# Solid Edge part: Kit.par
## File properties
Author: bmolnar
Last saved by: bmolnar
Revision: 78
Sűrűség: 0,000 kg/m^3
Pontosság: 0,990
Username: bmolnar
Dokumentum tartalom típus: 0
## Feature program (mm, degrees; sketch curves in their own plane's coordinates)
base feature "unnamed BaseFeature 1"
sketch for "unnamed Hole 1" plane through (36, 36, -84) normal (0, 0, -1) x-axis (0, -1, 0)
  hole centre (0, 0) bore radius 4.188
hole "unnamed Hole 1" through
sketch for "unnamed Hole 2" plane through (36, 36, -84) normal (0, 0, -1) x-axis (0, -1, 0)
  hole centre (0, 72) bore radius 4.188
hole "unnamed Hole 2" through
sketch for "unnamed Hole 3" plane through (36, 36, -84) normal (0, 0, -1) x-axis (0, -1, 0)
  hole centre (72, 72) bore radius 4.188
hole "unnamed Hole 3" through
sketch for "unnamed Hole 4" plane through (36, 36, -84) normal (0, 0, -1) x-axis (0, -1, 0)
  hole centre (72, 0) bore radius 4.188
hole "unnamed Hole 4" through
pattern "unnamed Pattern 1" of "unnamed Hole 1", "unnamed Hole 2", "unnamed Hole 3", "unnamed Hole 4"
sketch for "Furat_6" plane through (-47.6845, 0, -79.5) normal (-0.999962, 0, -0.008727) x-axis (0, -1, 0)
  hole centre (-0.0008, 0.4997) bore radius 4.283
hole "Furat_6" nominal diameter 9.728 finite  ThreadDepth = 10 mm
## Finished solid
Body 1: solid body, 307 faces, 739 edges, 449 vertices.
  Faces by surface: plane 139, cylinder 73, swept 60, cone 24, torus 10, spline 1
  Edges by curve: line 421, circle 152, spline 120, ellipse 32, curve on surface 14
Bounding box of the edges (mm; curved faces can reach further): 95.500 x 95.500 x 15.000, from (-47.75, -47.75, -87) to (47.75, 47.75, -72).
Cylindrical faces by radius (mm): R0.2 x48, R0.2017 x2, R0.2018 x2, R4.188 x4, R4.283 x1, R4.9 x4, R5.15 x4, R6.75 x4, R10.3 x1, R10.95 x1, R11.5 x1, R12.5 x1
Conical faces (half-angle, radius in mm at the cone's reference point): 0.5 deg R10 x4, 0.5 deg R13.5 x2, 7 deg R11.7695 x1, 14 deg R10.15 x1, 14 deg R10.557 x1, 17 deg R10.15 x1, 23 deg R10.9211 x1, 42.5 deg R10.137 x1, 45 deg R4.185 x4, 45 deg R4.985 x4, 45 deg R11.1 x1, 84 deg R10.512 x1, 85 deg R12.1625 x1, 87 deg R10.2157 x1
Toroidal faces (ring radius, tube radius in mm): R4.7 r0.2 x8, R10.9008 r0.225 x1, R11.3914 r0.325 x1
Planar faces by outward normal: +x 14, +y 14, +z 1, -x 16, -y 13, -z 19, oblique 62
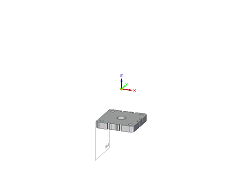
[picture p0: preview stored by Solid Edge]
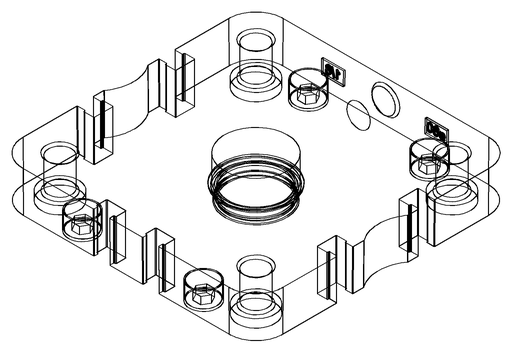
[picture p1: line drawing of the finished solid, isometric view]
